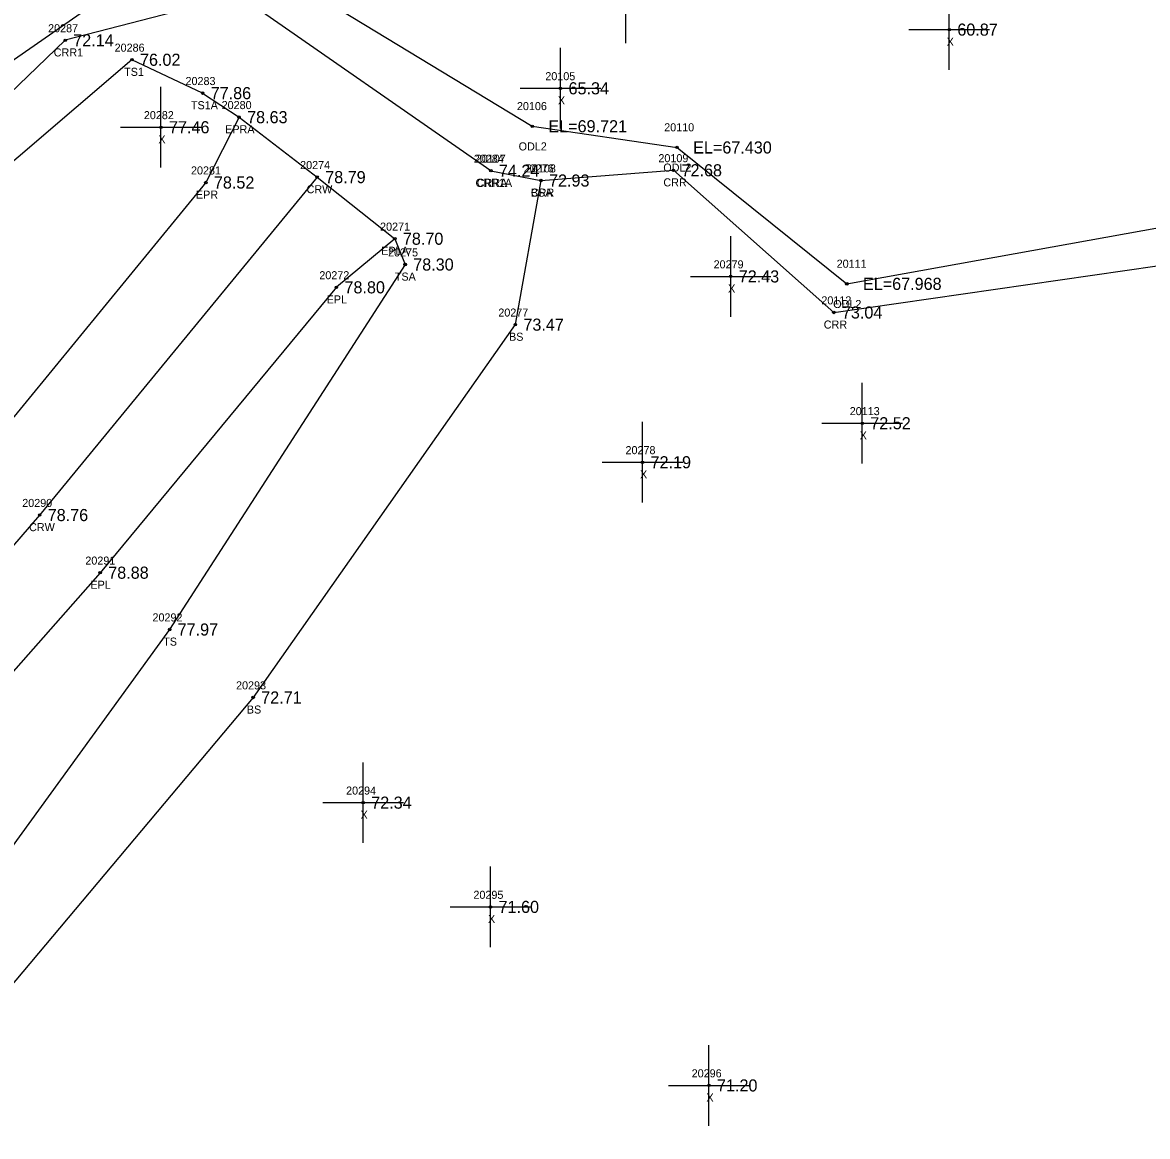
# Model space of a CAD drawing. Extents: x 2505300 to 2506184, y 912965 to 913825.
# Drawn here: x 2505731.4 to 2505870.9, y 913344.5 to 913482.7 of the extents above; entities that cross this region are included whole.
import ezdxf

# ---------------------------------------------------------------- set-up
doc = ezdxf.new("R2010")
doc.units = 0
for name, color, linetype in [('RD_DTM_BkLn1', 7, 'Continuous'), ('RD_DTM_BkLn2', 7, 'Continuous'), ('RD_DTM_BkLn_txCode', 7, 'Continuous'), ('RD_EX_H2O', 7, 'Continuous'), ('RD_EX_H2O_txCode', 7, 'Continuous'), ('RD_EX_Misc', 7, 'Continuous'), ('RD_EX_Misc_txCode', 7, 'Continuous'), ('RD_EX_Road', 7, 'Continuous'), ('RD_EX_Road_txCode', 7, 'Continuous'), ('RD_EX_TX_H2O_ELEV', 7, 'Continuous'), ('RD_EX_TX_Misc_ELEV', 7, 'Continuous'), ('RD_EX_TX_Road_ELEV', 7, 'Continuous'), ('RD_HC_Survey_ELEV', 7, 'Continuous'), ('RD_HC_Survey_txCode', 7, 'Continuous'), ('RD_SMD_Locator', 7, 'Continuous')]:
    doc.layers.add(name, color=color, linetype=linetype)

msp = doc.modelspace()

# ---------------------------------------------------------------- linework, layer by layer
at = {"layer": 'RD_DTM_BkLn1'}
for points in [[(2505753.71, 913473.94), (2505758.23, 913470.96), (2505767.92, 913463.52), (2505777.56, 913455.88), (2505778.84, 913452.68)], [(2505767.92, 913463.52), (2505733.49, 913421.6), (2505698.21, 913380.67), (2505657.08, 913336.16), (2505615.28, 913294.08), (2505578.04, 913257.66), (2505509.81, 913190.87), (2505437.56, 913120.73), (2505363.23, 913048.54)]]:
    msp.add_lwpolyline(points, dxfattribs=at)
at = {"layer": 'RD_DTM_BkLn2'}
for points in [[(2505753.71, 913473.94), (2505744.94, 913478.08), (2505723.86, 913460.1), (2505705.31, 913435.28), (2505675.97, 913399.31), (2505635.15, 913352.85), (2505596.03, 913310.85), (2505561.37, 913275.87), (2505492.57, 913207.56), (2505417.69, 913144.74), (2505344.31, 913068.67)], [(2505795.69, 913463.1), (2505792.51, 913445.22), (2505759.98, 913398.97), (2505723.99, 913356.17), (2505679.61, 913316.33), (2505634.47, 913275.19), (2505602.54, 913232.97), (2505592.24, 913228.82), (2505620.93, 913209.9)], [(2505778.84, 913452.68), (2505749.61, 913407.4), (2505717.38, 913363.03), (2505676.27, 913319.47), (2505630.56, 913278.36), (2505596.33, 913240.71), (2505582.14, 913231.32), (2505618.19, 913208.73)]]:
    msp.add_lwpolyline(points, dxfattribs=at)
at = {"layer": 'RD_EX_H2O'}
for points in [[(2505660.9, 913411.21), (2505684.62, 913438.72), (2505715.28, 913467.7), (2505742.46, 913486.6), (2505763.96, 913488.43), (2505794.61, 913469.83), (2505812.57, 913467.2), (2505833.64, 913450.28), (2505872.88, 913457.34), (2505893.17, 913479.86), (2505942.46, 913480.08), (2505995.98, 913475.04), (2506045.33, 913460.93), (2506077.87, 913439.29), (2506087.99, 913429.78), (2506108.19, 913381.27)], [(2505789.47, 913464.31), (2505758.18, 913486.1), (2505736.66, 913480.49), (2505719.32, 913463.86), (2505699.9, 913439.21), (2505669.03, 913402.75), (2505628.5, 913357.9), (2505593, 913316.39), (2505556.58, 913279.8), (2505487.72, 913211.38), (2505413.81, 913149.81), (2505341.31, 913072.1)], [(2505789.47, 913464.31), (2505795.69, 913463.1), (2505812.13, 913464.37), (2505832.03, 913446.73), (2505876.17, 913453.08), (2505891.76, 913474.03), (2505941.74, 913475.13), (2505995.42, 913465.05), (2506040.13, 913447.4), (2506076.3, 913432.47), (2506096.96, 913385.48)]]:
    msp.add_lwpolyline(points, dxfattribs=at)
at = {"layer": 'RD_EX_Misc'}
for p, q in [((2505806.23, 913480.13), (2505806.23, 913490.13)), ((2505846.35, 913476.82), (2505846.35, 913486.82)), ((2505841.35, 913481.82), (2505851.35, 913481.82)), ((2505798.11, 913469.54), (2505798.11, 913479.54)), ((2505748.54, 913464.71), (2505748.54, 913474.71)), ((2505793.11, 913474.54), (2505803.11, 913474.54)), ((2505743.54, 913469.71), (2505753.54, 913469.71)), ((2505819.23, 913446.2), (2505819.23, 913456.2)), ((2505814.23, 913451.2), (2505824.23, 913451.2)), ((2505835.55, 913427.99), (2505835.55, 913437.99)), ((2505808.29, 913423.15), (2505808.29, 913433.15)), ((2505830.55, 913432.99), (2505840.55, 913432.99)), ((2505803.29, 913428.15), (2505813.29, 913428.15)), ((2505773.63, 913380.92), (2505773.63, 913390.92)), ((2505768.63, 913385.92), (2505778.63, 913385.92)), ((2505789.43, 913367.99), (2505789.43, 913377.99)), ((2505784.43, 913372.99), (2505794.43, 913372.99)), ((2505816.53, 913345.84), (2505816.53, 913355.84)), ((2505811.53, 913350.84), (2505821.53, 913350.84))]:
    msp.add_line(p, q, dxfattribs=at)
at = {"layer": 'RD_EX_Road'}
for points in [[(2505758.23, 913470.96), (2505754.11, 913462.85), (2505725.4, 913427.85), (2505690.77, 913387.11), (2505650.25, 913343.36), (2505607.72, 913300.12), (2505570.97, 913264.99), (2505501.53, 913196.72), (2505431.76, 913128.83), (2505356.25, 913055.37)], [(2505777.56, 913455.88), (2505770.31, 913449.85), (2505741, 913414.45), (2505705.55, 913374.27), (2505664.83, 913329.82), (2505624.02, 913288.23), (2505585.62, 913250.63), (2505516.95, 913183.5), (2505444.27, 913113.56), (2505370.6, 913041.78)]]:
    msp.add_lwpolyline(points, dxfattribs=at)
at = {"layer": 'RD_SMD_Locator'}
for centre in [(2505846.35, 913481.82), (2505736.66, 913480.49), (2505744.94, 913478.08), (2505753.71, 913473.94), (2505798.11, 913474.54), (2505758.23, 913470.96), (2505748.54, 913469.71), (2505794.61, 913469.83), (2505812.57, 913467.2), (2505789.47, 913464.31), (2505789.47, 913464.31), (2505812.13, 913464.37), (2505754.11, 913462.85), (2505767.92, 913463.52), (2505795.69, 913463.1), (2505795.69, 913463.1), (2505777.56, 913455.88), (2505778.84, 913452.68), (2505819.23, 913451.2), (2505770.31, 913449.85), (2505833.64, 913450.28), (2505832.03, 913446.73), (2505792.51, 913445.22), (2505835.55, 913432.99), (2505808.29, 913428.15), (2505733.49, 913421.6), (2505741, 913414.45), (2505749.61, 913407.4), (2505759.98, 913398.97), (2505773.63, 913385.92), (2505789.43, 913372.99), (2505816.53, 913350.84)]:
    msp.add_circle(centre, 0.15, dxfattribs=at)

# ---------------------------------------------------------------- texts
at = {"layer": 'RD_DTM_BkLn_txCode'}
for s, p in [('20286', (2505742.79, 913479.08)), ('TS1', (2505743.97, 913476.08)), ('20283', (2505751.59, 913474.94)), ('TS1A', (2505752.26, 913471.94)), ('20276', (2505793.55, 913464.1)), ('BSA', (2505794.43, 913461.1)), ('20275', (2505776.72, 913453.68)), ('TSA', (2505777.56, 913450.68)), ('20277', (2505790.4, 913446.22)), ('BS', (2505791.73, 913443.22)), ('20292', (2505747.49, 913408.4)), ('TS', (2505748.82, 913405.4)), ('20293', (2505757.86, 913399.97)), ('BS', (2505759.2, 913396.97))]:
    msp.add_text(s, height=1, dxfattribs=at).set_placement(p)
at = {"layer": 'RD_EX_H2O_txCode'}
for s, p in [('20287', (2505734.54, 913481.49)), ('CRR1', (2505735.24, 913478.49)), ('20106', (2505792.71, 913471.83)), ('20110', (2505810.98, 913469.2)), ('ODL2', (2505792.92, 913466.83)), ('20284', (2505787.36, 913465.31)), ('20107', (2505787.6, 913465.31)), ('20109', (2505810.26, 913465.37)), ('ODL2', (2505810.87, 913464.2)), ('20108', (2505793.82, 913464.1)), ('CRR1A', (2505787.57, 913462.31)), ('CRRA', (2505787.73, 913462.31)), ('CRR', (2505810.88, 913462.37)), ('CRR', (2505794.44, 913461.1)), ('20111', (2505832.38, 913452.28)), ('20112', (2505830.48, 913447.73)), ('ODL2', (2505831.95, 913447.28)), ('CRR', (2505830.78, 913444.73))]:
    msp.add_text(s, height=1, dxfattribs=at).set_placement(p)
at = {"layer": 'RD_EX_Misc_txCode'}
for s, p in [('X', (2505846.03, 913479.82)), ('20105', (2505796.23, 913475.54)), ('X', (2505797.79, 913472.54)), ('20282', (2505746.42, 913470.71)), ('X', (2505748.22, 913467.71)), ('20279', (2505817.11, 913452.2)), ('X', (2505818.91, 913449.2)), ('20113', (2505834, 913433.99)), ('X', (2505835.24, 913430.99)), ('20278', (2505806.18, 913429.15)), ('X', (2505807.98, 913426.15)), ('20294', (2505771.51, 913386.92)), ('X', (2505773.31, 913383.92)), ('20295', (2505787.31, 913373.99)), ('X', (2505789.12, 913370.99)), ('20296', (2505814.39, 913351.84)), ('X', (2505816.22, 913348.84))]:
    msp.add_text(s, height=1, dxfattribs=at).set_placement(p)
at = {"layer": 'RD_EX_Road_txCode'}
for s, p in [('20280', (2505756.07, 913471.96)), ('EPRA', (2505756.51, 913468.96)), ('20281', (2505752.27, 913463.85)), ('EPR', (2505752.88, 913460.85)), ('20271', (2505775.73, 913456.88)), ('EPLA', (2505775.87, 913453.88)), ('20272', (2505768.19, 913450.85)), ('EPL', (2505769.1, 913447.85)), ('20291', (2505739.16, 913415.45)), ('EPL', (2505739.79, 913412.45))]:
    msp.add_text(s, height=1, dxfattribs=at).set_placement(p)
at = {"layer": 'RD_EX_TX_H2O_ELEV'}
for s, p in [('72.14', (2505737.66, 913479.74)), ('EL=69.721', (2505796.61, 913469.08)), ('EL=67.430', (2505814.57, 913466.45)), ('74.24', (2505790.47, 913463.56)), ('74.24', (2505790.47, 913463.56)), ('72.93', (2505796.69, 913462.35)), ('72.68', (2505813.13, 913463.62)), ('EL=67.968', (2505835.64, 913449.53)), ('73.04', (2505833.03, 913445.98))]:
    msp.add_text(s, height=1.5, dxfattribs=at).set_placement(p)
at = {"layer": 'RD_EX_TX_Misc_ELEV'}
for s, p in [('60.87', (2505847.35, 913481.07)), ('76.02', (2505745.94, 913477.33)), ('65.34', (2505799.11, 913473.79)), ('77.86', (2505754.71, 913473.19)), ('77.46', (2505749.54, 913468.96)), ('72.93', (2505796.69, 913462.35)), ('78.30', (2505779.84, 913451.93)), ('72.43', (2505820.23, 913450.45)), ('73.47', (2505793.51, 913444.47)), ('72.52', (2505836.55, 913432.24)), ('72.19', (2505809.29, 913427.4)), ('77.97', (2505750.61, 913406.65)), ('72.71', (2505760.98, 913398.22)), ('72.34', (2505774.63, 913385.17)), ('71.60', (2505790.43, 913372.24)), ('71.20', (2505817.53, 913350.09))]:
    msp.add_text(s, height=1.5, dxfattribs=at).set_placement(p)
at = {"layer": 'RD_EX_TX_Road_ELEV'}
for s, p in [('78.63', (2505759.23, 913470.21)), ('78.52', (2505755.11, 913462.1)), ('78.70', (2505778.56, 913455.13)), ('78.80', (2505771.31, 913449.1)), ('78.88', (2505742, 913413.7))]:
    msp.add_text(s, height=1.5, dxfattribs=at).set_placement(p)
at = {"layer": 'RD_HC_Survey_ELEV'}
for s, p in [('78.79', (2505768.92, 913462.77)), ('78.76', (2505734.49, 913420.85))]:
    msp.add_text(s, height=1.5, dxfattribs=at).set_placement(p)
at = {"layer": 'RD_HC_Survey_txCode'}
for s, p in [('20274', (2505765.81, 913464.52)), ('CRW', (2505766.61, 913461.52)), ('20290', (2505731.33, 913422.6)), ('CRW', (2505732.18, 913419.6))]:
    msp.add_text(s, height=1, dxfattribs=at).set_placement(p)

doc.saveas('drawing.dxf')
